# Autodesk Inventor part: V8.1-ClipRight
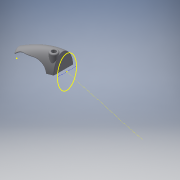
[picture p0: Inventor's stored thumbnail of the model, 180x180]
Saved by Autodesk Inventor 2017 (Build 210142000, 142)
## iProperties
Created: 2015-10
Part Number: V8.1-ClipRight
Material: Generic
Document SubType Name: Modeling
Designer: Luke Denby
Density: 1 g/cm^3
Appearance: Default
Author: Luke Denby
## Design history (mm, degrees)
workplane "Work Plane3"
sketch "Front"
  geometry: L1 (15, -25)-(-15, -25); L2 (-15, -25)-(-15, 25); L3 (-15, 25)-(15, 25); L4 (15, 25)-(15, -25); L5 (0, -25)-(0, 25); L6 (-15, 0)-(15, 0); 2 further points
  constraints: 12 end point, 6 midpoint, 2 parallel, 2 perpendicular, 1 coincident, 1 horizontal, 4 other
  dimensions: "d3" = 30 distance of L6.start L6.end; "d8" = 50 distance of L5.start L5.end
sketch "End" dims "d15" = 8, "d16" = 8
  geometry: L1 (10, 17)-(10, -13); L2 (24, 0)-(-0.308, 0); 6 further points; 1 other entity
  constraints: 4 end point, 4 point on line, 1 horizontal, 1 vertical, 6 other
sketch "Sides" dims "d40" = 16 (derived)
sketch "Top"
node "3D Sketch8"
sketch "Bottom"
loft "Loft1" sketch "Bottom" dims "d17" = 0, "d18" = 90 deg, "d19" = 0, "d20" = 90 deg, "d21" = 0, "d22" = 90 deg, "d23" = 0, "d24" = 90 deg, "d25" = 0, "d26" = 90 deg, "d53" = 0, "d54" = 90 deg
fillet "Fillet3" dims "d29" = 6
sketch "Angle Line"
  geometry: L1 (151, -33)-(0, 0)
  constraints: 2 end point
workplane "Work Plane8"
node "3D Sketch11"
sketch "Sketch14"
  geometry: L1 (-1.282, 2.515)-(1.536, 2.515); L2 (1.536, 2.515)-(1.536, -1.569); L3 (1.536, -1.569)-(-1.282, -1.569); L4 (-1.282, -1.569)-(-1.282, 2.515); 1 further point
  constraints: 2 other
extrude "Version Number" cut sketch "Sketch14" distance "d57" = 2; taper "d58" = 0 deg
sketch "Sketch16"
  geometry: 1 further point
workplane "Work Plane10"
sketch "Sketch20"
  geometry: L1 (-24, -28)-(28, -28); 1 further point
  constraints: 2 end point, 1 horizontal
node "Clip End Work Plane"
sketch "Sketch25"
  geometry: 1 further point
sketch "Clip Front"
  geometry: L1 (9, 7.5)-(39, 7.5); L2 (24, 20)-(24, -5); 4 further points
  constraints: 4 end point, 3 midpoint, 1 coincident, 1 horizontal, 1 point on line, 1 vertical, 7 other
  dimensions: "d73" = 30 distance of L1.start point (39, 7.5); "d74" = 25 distance of L2.end L2.start
sketch "Clip Sides"
sketch "Clip Top"
  geometry: L1 (0, 15)-(-40, 11); L2 (-40, 11)-(-61.841, -9.206); L3 (-61.841, -9.206)-(-53.29, -32.698) reference; 2 further points
  constraints: 1 coincident, 3 other
sketch "Sketch24"
  geometry: L1 (0, 15)-(0, -15); 1 further point
  constraints: 2 end point, 1 vertical, 1 vertical alignment, 1 other
sketch "Clip Bottom"
  geometry: L1 (0, -15)-(-34.83, -29.214); L2 (-34.83, -29.214)-(-53.29, -32.698); L3 (0, 15)-(0, -15) reference; 2 further points
  constraints: 1 coincident, 3 other
loft "Clip" sketch "Clip Bottom" dims "d75" = 0, "d76" = 90 deg, "d77" = 0, "d78" = 90 deg, "d79" = 0, "d80" = 90 deg, "d81" = 0, "d82" = 90 deg, "d83" = 0, "d84" = 90 deg, "d85" = 0, "d86" = 90 deg
  node "Edges1"
workplane "Work Plane12"
sketch "Clip Hole Sketch"
  geometry: L1 (39, 0)-(9, 0) reference; L2 (24, -194.931)-(24, 89.069); L3 (14, 8.871)-(14, -26.129); L4 (34, 8.871)-(34, -26.129); A1 r 10 centre (24, -26.129) between (24, -36.129) and (14, -26.129); A2 r 10 centre (24, 8.871) between (24, 18.871) and (14, 8.871); 6 further points
  constraints: 6 end point, 6 point on circle, 6 point on line, 4 tangent, 2 centre point, 1 midpoint, 1 vertical, 2 other
  dimensions: "d88" = 20 diameter of A1; "d141" = 20 diameter of A2; "d142" = 55 distance of A2.start A1.start; "d145" = 30 distance of A1.centre point (24, -56.129)
sketch "Sketch27"
  geometry: C1 r 2.25 at (0, -12); 1 further point
  constraints: 1 centre point, 1 vertical alignment
  dimensions: "d93" = 4.5 diameter of C1; "d95" = 12 distance of point (0, 0) C1.centre
extrude "Screw Holes Handle" cut sketch "Sketch27" distance "d97" = 12; taper "d99" = 0 deg; dims "d98" = 20, "d100" = 0
node "Counterbore Workplane"
sketch "Sketch28"
  geometry: C1 r 4.5 at (0, -12); C2 r 4.5 at (0, 12); 1 further point
  constraints: 2 centre point, 2 vertical alignment
  dimensions: "d102" = 9 diameter of C2; "d103" = 12 distance of point (0, 0) C1.centre; "d104" = 12 distance of C2.centre point (0, 0); "d128" = 9 diameter of C1
extrude "Counterbore" cut sketch "Sketch28" distance "d180" = 15; taper "d181" = 0 deg
sketch "Sketch29"
  geometry: C1 r 2.8 at (0, -12); C2 r 2.8 at (0, 12); 1 further point
  constraints: 2 centre point, 2 vertical alignment
  dimensions: "d107" = 5.6 diameter of C1; "d109" = 12 distance of point (0, 0) C1.centre; "d197" = 5.6 diameter of C2 (derived); "d198" = 12 distance of C2.centre point (0, 0)
extrude "Screw Holes Clip" cut sketch "Sketch29" stored distance "d110" = 20; taper "d111" = 0 deg
workplane "Work Plane14"
fillet "Fillet8" dims "d125" = 4
extrude "Clip Hole" cut sketch "Clip Hole Sketch" stored distance "d143" = 10; taper "d144" = 0 deg
fillet "Fillet14" dims "d146" = 1
sketch "Handle Cut Off Sketch"
  geometry: L1 (-170, -40)-(0, -40); L2 (0, -40)-(0, 40); L3 (0, 40)-(-170, 40); L4 (-170, 40)-(-170, -40); L5 (-170, -40)-(0, 40); L6 (0, -40)-(-170, 40); 4 further points
  constraints: 12 end point, 3 midpoint, 2 parallel, 1 horizontal, 1 horizontal alignment, 1 perpendicular, 1 point on line
  dimensions: "d112" = 80 distance of L3.end L1.start; "d113" = 170 distance of L2.end L3.end
sketch "Clip Cut Off Sketch"
  geometry: L1 (74, 41)-(0, 41); L2 (0, 41)-(0, -41); L3 (0, -41)-(74, -41); L4 (74, -41)-(74, 41); L5 (74, 41)-(0, -41); L6 (0, 41)-(74, -41); L7 (-165.272, 0)-(74, 0); L8 (-170, -40)-(0, -40) reference; L9 (0, -40)-(0, 40) reference; 4 further points
  constraints: 14 end point, 4 midpoint, 2 parallel, 1 horizontal, 1 perpendicular, 1 point on line
  dimensions: "d133" = 74 distance of L2.end L3.end; "d134" = 82 distance of L3.end L1.start; "d136" = 40 distance between parallel lines of L7 L8
workplane "Work Plane15"
workplane "Work Plane16"
sketch "Slot Top"
  geometry: L1 (24, -216.564)-(24, 8.278) reference; L2 (38.5, -26.129)-(9.5, -26.129); L3 (38.5, -15.129)-(9.5, -15.129); L4 (38.5, -26.129)-(38.5, -15.129); L5 (9.5, -26.129)-(9.5, -15.129); A1 r 14.5 centre (24, -26.129) between (9.5, -26.129) and (38.5, -26.129); A2 r 14.5 centre (24, -15.129) between (38.5, -15.129) and (9.5, -15.129); 1 further point
  constraints: 8 end point, 4 point on circle, 2 centre point, 2 midpoint, 1 horizontal, 1 perpendicular, 1 point on line
  dimensions: "d154" = 29 diameter of A2; "d155" = 29 diameter of A1; "d156" = 40 dimension on A2 A1
sketch "Slot Bottom"
  geometry: L1 (24, -42.379)-(24, 3.621); L2 (7.75, -26.129)-(7.75, -12.629); L3 (7.75, -26.129)-(39.868, -26.129); L4 (7.75, -12.629)-(40.25, -12.629); L5 (40.25, -26.129)-(40.25, -12.629); A1 r 16.25 centre (24, -26.129) between (7.75, -26.129) and (40.25, -26.129); A2 r 16.25 centre (24, -12.629) between (40.25, -12.629) and (7.75, -12.629); 2 further points
  constraints: 10 end point, 6 point on circle, 3 point on line, 2 centre point, 2 horizontal, 2 tangent, 1 coincident, 1 vertical, 1 vertical alignment
  dimensions: "d157" = 32.5 diameter of A1; "d158" = 32.5 diameter of A2; "d159" = 46 distance of L1.end L1.start
loft "Bottle Slot" sketch "Slot Bottom" dims "d160" = 0, "d161" = 90 deg, "d162" = 0, "d163" = 90 deg
sketch "Sketch39"
  geometry: C1 r 34.655 at (0, 0); 1 further point
  constraints: 1 centre point
extrude "Extrusion18" cut sketch "Sketch39" distance "d170" = 40; taper "d171" = 0 deg
fillet "Fillet17" dims "d172" = 10
workplane "Work Plane17"
sketch "Sketch40"
  geometry: C1 r 2.5 at (-10, -10); 2 further points
  constraints: 1 centre point, 1 horizontal alignment
  dimensions: "d176" = 5 diameter of C1; "d228" = 10 horizontal distance of point (0, 0) C1.centre; "d229" = 10 horizontal distance of point (0, 0) C1.centre
extrude "Threaded Hole" cut sketch "Sketch40" distance "d178" = 50; taper "d179" = 0 deg
sketch "Sketch41"
  geometry: C1 r 6 at (-10, -10); C2 r 1.65 at (-10, -10); 3 further points
  constraints: 3 coincident, 2 centre point, 2 other
  dimensions: "d183" = 12 diameter of C1; "d184" = 3.3 diameter of C2
extrude "Collar" join sketch "Sketch41" stored distance "d186" = 15; taper "d187" = 0 deg
fillet "Collar Fillet" dims "d251" = 2
workplane "Work Plane18"
sketch "Sketch45"
  geometry: C1 r 2.5 at (-10, -10) reference; C2 r 3.3 at (-10, -10); 1 further point
  constraints: 1 centre point, 1 coincident
  dimensions: "d215" = 6.6 diameter of C2
extrude "Threaded Clearance Hole" cut sketch "Sketch45" stored distance "d216" = 28; taper "d217" = 0 deg
fillet "Collar Inner Fillet" dims "d252" = 0.8
fillet "Fillet20" dims "d219" = 0.9
fillet "Fillet22" dims "d221" = 1
sketch "Sketch46"
  geometry: C1 r 3.3 at (-10, -10) reference; C2 r 4.3 at (-10, -10); 1 further point
  constraints: 1 centre point, 1 coincident
  dimensions: "d222" = 8.6 diameter of C2
extrude "Spring Burrow" cut sketch "Sketch46" distance "d223" = 8; taper "d224" = 0 deg
extrude "Handle Cut Off" cut sketch "Handle Cut Off Sketch" stored distance "d230" = 5; taper "d231" = 0 deg
sketch "Sketch49"
  geometry: C1 r 2.8 at (0, 12); 1 further point
  constraints: 1 centre point, 1 vertical alignment
  dimensions: "d232" = 12 distance of C1.centre point (0, 0); "d233" = 5.6 diameter of C1
extrude "Countersunk Screw Hole Clip" cut sketch "Sketch49" distance "d234" = 4; taper "d235" = 0 deg
extrude "Neatening Sketch" cut sketch "Slot Top" distance "d239" = 10; taper "d240" = 0 deg
sketch "Sketch50"
  geometry: L1 (0, 0)-(-41, 0); C1 r 3.3 at (-10, 7); C2 r 2.5 at (-10, -10) reference
  constraints: 2 end point, 1 centre point, 1 horizontal, 1 vertical alignment
  dimensions: "d243" = 6.6 diameter of C1; "d246" = 7 distance from line of L1 C1.centre
extrude "Locating Pin Hole" cut sketch "Sketch50" distance "d247" = 12; taper "d249" = 0 deg; dims "d248" = 8, "d250" = 0
sketch "Clip R+L Cutoff Sketch"
  geometry: L1 (4, 0)-(70, 0); L2 (70, 0)-(70, -35); L3 (70, -35)-(0, -35); L4 (0, -35)-(0, 0); L5 (0, 0)-(0, 35); L6 (0, 35)-(70, 35); L7 (70, 35)-(70, 0); L8 (4, 0)-(4, 35); L9 (0, 0)-(70, 0); L10 (70, 1)-(4, 1)
  constraints: 21 end point, 8 perpendicular, 3 point on line, 2 horizontal, 1 vertical
  dimensions: "d190" = 70 distance between parallel lines of L4 L2; "d191" = 35 distance of L3.end L4.end; "d192" = 35 distance between parallel lines of L6 L1; "d236" = 4 distance between parallel lines of L8 L5; "d238" = 1 distance between parallel lines of L10 L1
sketch "Sketch51"
  geometry: C1 r 3.3 at (-10, 7) reference; C2 r 3.55 at (-10, 7); 1 further point
  constraints: 1 centre point, 1 coincident
  dimensions: "d253" = 7.1 diameter of C2
extrude "Locating Pin Clearence Hole" cut sketch "Sketch51" distance "d254" = 12; taper "d255" = 0 deg
extrude "Extrusion39" cut sketch "Clip R+L Cutoff Sketch" stored distance "d256" = 10; taper "d257" = 0 deg
fillet "Fillet25" dims "d258" = 1
body "Solid2"
node "Projected Loop1"
other parameters: "d46" = 90 deg, "d69" = 55, "d72" = 20 deg, "d87" = 90 deg, "d152" = 8, "d153" = -26, "d175" = 28, "d189" = 16
